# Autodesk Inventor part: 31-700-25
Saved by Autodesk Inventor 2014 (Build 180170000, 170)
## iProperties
Company: TraceParts S.A.
Created: 2015-09
Part Number: 31-700-25
Checked By: TraceParts S.A.
Catalog Web Link: www.traceparts.com
Vendor: Emile Maurin
Document SubType Name: Modeling
Designer: TraceParts
Material: Générique
Density: 1 g/cm^3
Appearance: 176,176,176
REFERENCE: 31-700-25
SUPPLIER: Emile Maurin
TraceParts.PartNumber: 10-06082008-153027
TraceParts.PartTitle: 31-70 : BAGUE D'ARRÊT ACIER - DIN 705
TraceParts.InstanceId: 10-06082008-153027B330PWUX6LHG2MR5O2VQYQ38J
TraceParts.PartStatus: Published
TraceParts.PartVersion: 1.2.6
TRACEPARTS: TRACEPARTS
TraceParts.PartLanguage: fr
TraceParts.ClassPath: EMILE_MAURIN:/ESM/MONTAGE_e_1/SERIE_31_e_2/TYPE_311_e_3/10-06082008-153027
Author: TraceParts
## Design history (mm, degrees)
feature "31-700-25"
node "Solide1"
node "Corps solides"
node "Corps surfaciques"
